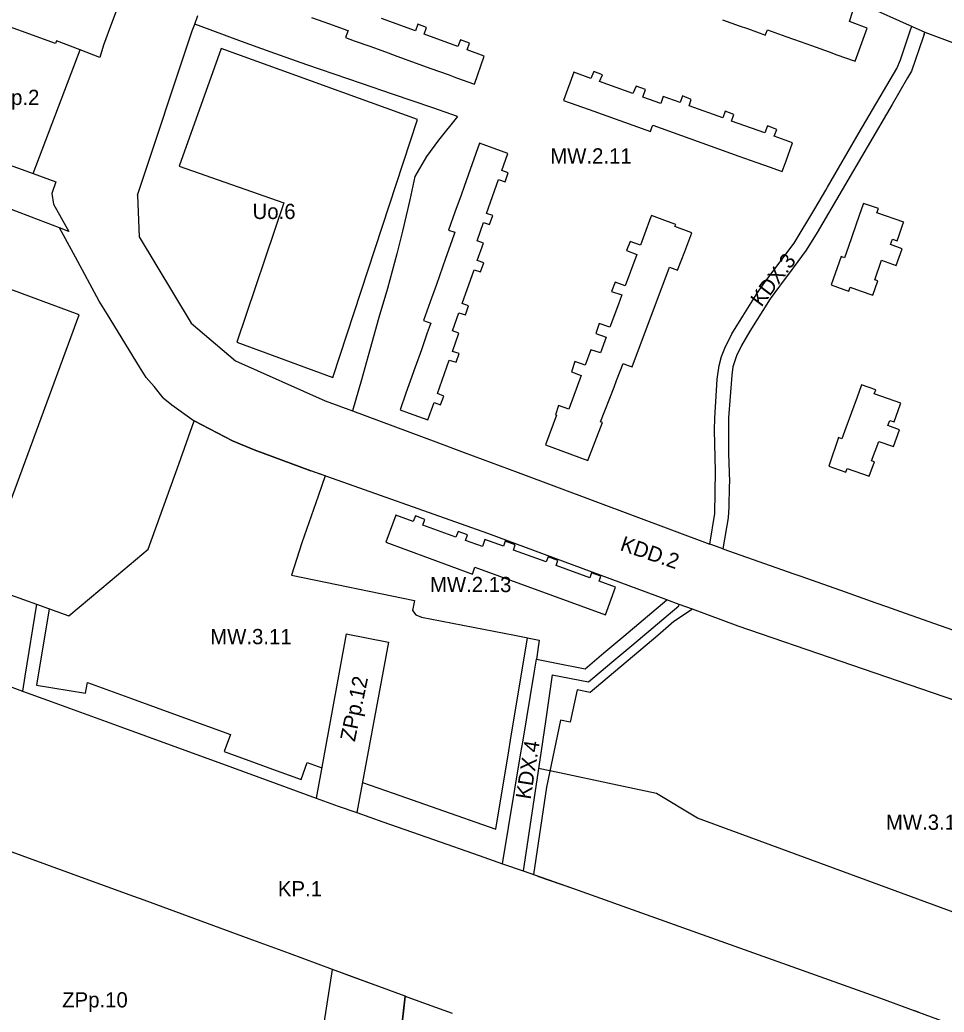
# Model space of a CAD drawing. Extents: x 7428239 to 7429836, y 5549133 to 5550853.
# Drawn here: x 7429012.7 to 7429316.4, y 5549745.6 to 5550071.7 of the extents above; entities that cross this region are included whole.
import ezdxf

# ---------------------------------------------------------------- set-up
doc = ezdxf.new("R2010")
doc.units = 0
for name, color, linetype in [('LIN_linia regulacyjna', 7, 'Continuous'), ('LIN_linie rozgraniczające', 7, 'Continuous'), ('LIN_nieprzekraczalna linia zabudowy', 7, 'Continuous'), ('LIN_obowiązująca linia zabudowy', 7, 'Continuous'), ('TXT_Oznaczenia Przeznaczenia', 7, 'Continuous')]:
    doc.layers.add(name, color=color, linetype=linetype)

msp = doc.modelspace()

# ---------------------------------------------------------------- linework, layer by layer
at = {"layer": 'LIN_linia regulacyjna'}
msp.add_lwpolyline([(7429383.84, 5549754.68), (7429367.89, 5549760.56), (7429360.9, 5549763.13), (7429350.66, 5549766.9), (7429332.99, 5549773.42), (7429318.45, 5549778.77), (7429315.16, 5549779.99), (7429235.41, 5549809.37), (7429221.85, 5549817.44), (7429207.39, 5549820.5), (7429189.98, 5549824.19), (7429183.11, 5549825.65)], dxfattribs=at)
at = {"layer": 'LIN_linie rozgraniczające'}
for p, q in [((7429048.11, 5550084.81), (7429042.17, 5550068.75)), ((7429070.18, 5550070.29), (7429071.18, 5550073.05)), ((7429042.17, 5550068.75), (7429040.94, 5550065.41)), ((7429051.4, 5550014.04), (7429069.36, 5550068.06)), ((7429069.36, 5550068.06), (7429070.18, 5550070.29)), ((7429075.21, 5550068.44), (7429070.18, 5550070.29)), ((7429085.48, 5550064.6), (7429075.21, 5550068.44)), ((7429040.94, 5550065.41), (7429040.18, 5550063.37)), ((7429094.96, 5550061.21), (7429085.48, 5550064.6)), ((7429309.49, 5550065.94), (7429305.69, 5550054.82)), ((7429309.83, 5550066.93), (7429309.49, 5550065.94)), ((7429039.01, 5550059.28), (7429032.54, 5550061.79)), ((7429040.18, 5550063.37), (7429039.01, 5550059.28)), ((7429107, 5550056.94), (7429094.96, 5550061.21)), ((7429300.88, 5550055.73), (7429302.04, 5550058.54)), ((7429124.92, 5550050.79), (7429107, 5550056.94)), ((7429288.53, 5550034.67), (7429300.88, 5550055.73)), ((7429305.69, 5550054.82), (7429304.33, 5550052.57)), ((7429304.33, 5550052.57), (7429299.34, 5550043.86)), ((7429135.1, 5550047.26), (7429124.92, 5550050.79)), ((7429148.42, 5550042.73), (7429135.1, 5550047.26)), ((7429156.54, 5550039.96), (7429148.42, 5550042.73)), ((7429299.34, 5550043.86), (7429274.66, 5550001.79)), ((7429156.54, 5550039.96), (7429150.28, 5550032.18)), ((7429278.13, 5550016.7), (7429288.53, 5550034.67)), ((7429150.28, 5550032.18), (7429146.35, 5550026.77)), ((7429146.35, 5550026.77), (7429142.5, 5550020.18)), ((7429017.02, 5550021.18), (7429024.56, 5550018.47)), ((7429024.56, 5550018.47), (7429023.19, 5550014.63)), ((7429142.5, 5550020.18), (7429140.81, 5550012.55)), ((7429273.95, 5550009.54), (7429277.48, 5550015.75)), ((7429277.48, 5550015.75), (7429278.13, 5550016.7)), ((7429023.19, 5550014.63), (7429023.8, 5550011.07)), ((7429051.4, 5550014.04), (7429051.87, 5550000.33)), ((7429140.81, 5550012.55), (7429138.4, 5550002.19)), ((7429023.8, 5550011.07), (7429028.8, 5550002.15)), ((7429267.13, 5549998.27), (7429273.95, 5550009.54)), ((7429028.8, 5550002.15), (7429025.73, 5550003.32)), ((7429138.4, 5550002.19), (7429136.57, 5549994.79)), ((7429051.87, 5550000.33), (7429068.96, 5549971.95)), ((7429274.66, 5550001.79), (7429271.05, 5549996.04)), ((7429257.18, 5549985.08), (7429267.13, 5549998.27)), ((7429271.05, 5549996.04), (7429266.84, 5549990.22)), ((7429136.57, 5549994.79), (7429133.46, 5549983.4)), ((7429266.84, 5549990.22), (7429262.28, 5549984.21)), ((7429133.46, 5549983.4), (7429130.67, 5549973.83)), ((7429254.62, 5549981.31), (7429257.18, 5549985.08)), ((7429262.28, 5549984.21), (7429259.23, 5549979.97)), ((7429250.21, 5549974.3), (7429254.62, 5549981.31)), ((7429259.23, 5549979.97), (7429252.6, 5549969.35)), ((7429130.67, 5549973.83), (7429127.19, 5549961.24)), ((7429246.65, 5549968.52), (7429250.21, 5549974.3)), ((7429068.96, 5549971.95), (7429083.61, 5549959.58)), ((7429252.6, 5549969.35), (7429249.84, 5549964.65)), ((7429244.32, 5549963.81), (7429246.65, 5549968.52)), ((7429243.21, 5549961.01), (7429244.32, 5549963.81)), ((7429249.84, 5549964.65), (7429248.21, 5549961.23)), ((7429083.61, 5549959.58), (7429113.02, 5549946.53)), ((7429127.19, 5549961.24), (7429124.91, 5549953.41)), ((7429242.45, 5549958.06), (7429243.21, 5549961.01)), ((7429248.21, 5549961.23), (7429246.97, 5549957.62)), ((7429241.85, 5549953.58), (7429242.45, 5549958.06)), ((7429246.97, 5549957.62), (7429246.63, 5549954.94)), ((7429124.91, 5549953.41), (7429122.03, 5549943.17)), ((7429241.04, 5549940.77), (7429241.85, 5549953.58)), ((7429246.63, 5549954.94), (7429245.58, 5549940.93)), ((7429059.76, 5549947.51), (7429056.86, 5549951.14)), ((7429113.02, 5549946.53), (7429122.03, 5549943.17)), ((7429122.03, 5549943.17), (7429149.33, 5549932.99)), ((7429240.93, 5549936.89), (7429241.04, 5549940.77)), ((7429245.58, 5549940.93), (7429245.6, 5549929.22)), ((7429064.9, 5549925.71), (7429070.03, 5549939.93)), ((7429241.24, 5549923.35), (7429240.93, 5549936.89)), ((7429149.33, 5549932.99), (7429158.67, 5549929.51)), ((7429158.67, 5549929.51), (7429176.43, 5549922.89)), ((7429245.6, 5549929.22), (7429245.85, 5549919.81)), ((7429054.82, 5549897.74), (7429064.9, 5549925.71)), ((7429113.02, 5549921.82), (7429110.7, 5549915.13)), ((7429176.43, 5549922.89), (7429239.44, 5549899.39)), ((7429241.07, 5549909.41), (7429241.24, 5549923.35)), ((7429245.76, 5549918.47), (7429245.61, 5549911.62)), ((7429245.85, 5549919.81), (7429245.76, 5549918.47)), ((7429110.7, 5549915.13), (7429105.4, 5549899.79)), ((7429245.61, 5549911.62), (7429245.41, 5549908.03)), ((7429239.44, 5549899.39), (7429241.07, 5549909.41)), ((7429245.41, 5549908.03), (7429243.7, 5549897.84)), ((7429042.36, 5549887.26), (7429054.82, 5549897.74)), ((7429241.61, 5549898.58), (7429239.44, 5549899.39)), ((7429243.7, 5549897.84), (7429241.61, 5549898.58)), ((7429243.7, 5549897.84), (7429266.98, 5549889.64)), ((7429266.98, 5549889.64), (7429269.34, 5549888.81)), ((7429269.34, 5549888.81), (7429283.86, 5549883.69)), ((7429002.91, 5549885.17), (7429018.14, 5549879.67)), ((7429028.75, 5549875.82), (7429042.36, 5549887.26)), ((7429283.86, 5549883.69), (7429293.99, 5549880.12)), ((7429018.14, 5549879.67), (7429014.36, 5549856.01)), ((7429018.14, 5549879.67), (7429028.75, 5549875.82)), ((7429211.17, 5549869.14), (7429225.33, 5549881.09)), ((7429213.75, 5549866.08), (7429229.19, 5549879.11)), ((7429229.19, 5549879.11), (7429229.36, 5549879.6)), ((7429293.99, 5549880.12), (7429297.52, 5549878.87)), ((7429297.52, 5549878.87), (7429302.08, 5549877.27)), ((7429302.08, 5549877.27), (7429312.94, 5549873.44)), ((7429316.41, 5549849.25), (7429248.77, 5549872.41)), ((7429312.94, 5549873.44), (7429354.21, 5549858.95)), ((7429119.89, 5549869.93), (7429110.07, 5549815.93)), ((7429119.89, 5549869.93), (7429133.88, 5549867.16)), ((7429204.62, 5549863.62), (7429211.17, 5549869.14)), ((7429133.88, 5549867.16), (7429123.44, 5549811.15)), ((7429207.2, 5549860.56), (7429213.75, 5549866.08)), ((7429198.44, 5549858.41), (7429204.62, 5549863.62)), ((7429181.79, 5549857.64), (7429182.44, 5549861.59)), ((7429182.44, 5549861.59), (7429188.44, 5549860.39)), ((7429188.44, 5549860.39), (7429198.44, 5549858.41)), ((7429199.55, 5549854.11), (7429207.2, 5549860.56)), ((7428997.96, 5549856.76), (7429013.57, 5549851.08)), ((7429014.36, 5549856.01), (7429013.57, 5549851.08)), ((7429187.66, 5549856.47), (7429199.55, 5549854.11)), ((7429013.57, 5549851.08), (7429022.96, 5549847.66)), ((7429332.07, 5549843.85), (7429316.41, 5549849.25)), ((7429022.96, 5549847.66), (7429045.92, 5549839.3)), ((7429045.92, 5549839.3), (7429062.14, 5549833.39)), ((7429062.14, 5549833.39), (7429079.28, 5549827.15)), ((7429079.28, 5549827.15), (7429096.92, 5549820.72)), ((7429096.92, 5549820.72), (7429110.07, 5549815.93)), ((7429110.07, 5549815.93), (7429117.33, 5549813.3)), ((7429117.33, 5549813.3), (7429123.44, 5549811.15)), ((7429123.44, 5549811.15), (7429132.02, 5549808.15)), ((7429132.02, 5549808.15), (7429148.64, 5549802.33)), ((7429037.75, 5549788.14), (7429004.61, 5549800.21)), ((7429148.64, 5549802.33), (7429163.59, 5549797.08)), ((7429163.59, 5549797.08), (7429171.32, 5549794.37)), ((7429171.32, 5549794.37), (7429178.09, 5549791.99)), ((7429178.09, 5549791.99), (7429194.32, 5549786.31)), ((7429050.18, 5549783.61), (7429037.75, 5549788.14)), ((7429053.54, 5549782.38), (7429050.18, 5549783.61)), ((7429070.18, 5549776.25), (7429053.54, 5549782.38)), ((7429088.02, 5549769.69), (7429070.18, 5549776.25)), ((7429221.57, 5549776.61), (7429229.22, 5549773.89)), ((7429229.22, 5549773.89), (7429295.48, 5549750.16)), ((7429101.28, 5549764.81), (7429088.02, 5549769.69)), ((7429115.45, 5549759.59), (7429101.28, 5549764.81)), ((7429123.08, 5549756.78), (7429115.45, 5549759.59)), ((7429130.67, 5549753.98), (7429123.08, 5549756.78)), ((7429139.27, 5549750.82), (7429130.67, 5549753.98)), ((7429139.27, 5549750.82), (7429131.04, 5549678.2)), ((7429295.48, 5549750.16), (7429306.73, 5549746.05)), ((7429307.99, 5549745.59), (7429306.73, 5549746.05))]:
    msp.add_line(p, q, dxfattribs=at)
for points in [[(7429286.07, 5550078.43), (7429310.06, 5550067.61), (7429344.3, 5550054.83)], [(7429032.54, 5550061.79), (7429024.72, 5550064.82), (7429024.38, 5550063.89), (7429000.78, 5550072.42), (7428999.81, 5550074.51), (7428995.7, 5550075.64), (7428992.26, 5550076.61), (7428977.71, 5550035.34), (7428978.55, 5550035.04), (7429017.02, 5550021.18)], [(7429302.04, 5550058.54), (7429305.39, 5550068.36), (7429305.79, 5550069.53)], [(7429309.83, 5550066.93), (7429310.06, 5550067.61)], [(7429017.02, 5550021.18), (7429032.54, 5550061.79)], [(7429025.73, 5550003.32), (7429016.5, 5550006.84), (7428985.48, 5550018.65)], [(7429056.86, 5549951.14), (7429054.19, 5549954.17), (7429051.97, 5549957.62), (7429041.46, 5549974.82), (7429038.8, 5549979.23), (7429031.03, 5549993.68), (7429027.03, 5550000.92), (7429025.73, 5550003.32)], [(7429059.76, 5549947.51), (7429062.62, 5549945.15), (7429070.03, 5549939.93), (7429082.61, 5549933.34), (7429089.73, 5549930.32), (7429108.31, 5549923.49)], [(7429248.77, 5549872.41), (7429233.7, 5549877.99), (7429229.36, 5549879.6), (7429225.33, 5549881.09), (7429166.48, 5549902.88), (7429108.31, 5549923.49)], [(7429105.4, 5549899.79), (7429101.92, 5549889.21)], [(7429101.92, 5549889.21), (7429142.34, 5549880.86), (7429141.77, 5549877.61), (7429142.76, 5549876.11), (7429144.67, 5549875.41), (7429175.2, 5549869.43), (7429183.37, 5549867.81), (7429182.44, 5549861.59)], [(7429171.32, 5549794.37), (7429177.34, 5549830.76), (7429177.92, 5549834.28), (7429181.79, 5549857.64)], [(7429187.66, 5549856.47), (7429185.38, 5549841.12), (7429183.51, 5549828.49), (7429178.09, 5549791.99)], [(7429194.32, 5549786.31), (7429221.57, 5549776.61)], [(7429100.53, 5549677.21), (7429111.74, 5549735.61), (7429115.45, 5549759.59)], [(7429154.81, 5549745.13), (7429140.01, 5549750.55), (7429139.27, 5549750.82)]]:
    msp.add_lwpolyline(points, dxfattribs=at)
at = {"layer": 'LIN_nieprzekraczalna linia zabudowy'}
msp.add_line((7429083.95, 5549965.73), (7429115.51, 5549954.19), dxfattribs=at)
for points in [[(7429143.41, 5550038.92), (7429078.86, 5550062.23), (7429065.09, 5550023.61), (7429099.41, 5550011.58), (7429083.95, 5549965.73)], [(7429115.51, 5549954.19), (7429143.41, 5550038.92)], [(7429032.2, 5549974.74), (7428968.53, 5549998.27), (7428938.39, 5549916.68), (7429002.06, 5549893.16), (7429032.2, 5549974.74)], [(7429113.02, 5549921.82), (7429108.31, 5549923.49), (7429089.73, 5549930.32), (7429082.61, 5549933.34), (7429070.03, 5549939.93)], [(7429022.29, 5549878.16), (7429018.13, 5549853), (7429034.32, 5549850.46), (7429034.89, 5549853.96), (7429049.34, 5549848.7), (7429065.56, 5549842.79), (7429081.87, 5549836.85), (7429079.83, 5549831.21), (7429090.36, 5549827.38), (7429094.47, 5549825.9), (7429105.08, 5549822.03), (7429107.13, 5549827.64), (7429111.89, 5549825.91)], [(7429233.7, 5549877.99), (7429227.6, 5549873.93), (7429222.34, 5549869.33)], [(7429376.87, 5549828.41), (7429371.43, 5549830.28), (7429345.57, 5549839.2), (7429329.74, 5549844.65), (7429316.41, 5549849.25), (7429248.77, 5549872.41), (7429233.7, 5549877.99)], [(7429169.14, 5549805.73), (7429173.39, 5549831.41), (7429173.97, 5549834.93), (7429179.55, 5549868.57)], [(7429222.34, 5549869.33), (7429200.14, 5549850.62), (7429195.8, 5549851.51), (7429193.56, 5549840.86), (7429190.36, 5549841.52), (7429185.7, 5549819.51), (7429181.44, 5549790.82)], [(7429125.29, 5549821.1), (7429135.32, 5549817.59), (7429151.95, 5549811.77), (7429166.9, 5549806.52), (7429169.14, 5549805.73)], [(7429182.79, 5549790.32), (7429194.32, 5549786.31), (7429221.57, 5549776.61)], [(7429221.57, 5549776.61), (7429229.22, 5549773.89), (7429295.48, 5549750.16), (7429306.73, 5549746.05), (7429307.99, 5549745.59)], [(7429100.53, 5549677.21), (7429129.64, 5549666.8), (7429131.04, 5549678.2), (7429139.27, 5549750.82), (7429130.67, 5549753.98), (7429115.45, 5549759.59)], [(7429307.99, 5549745.59), (7429325.83, 5549739.04), (7429343.2, 5549732.68), (7429360.02, 5549726.52), (7429374.1, 5549721.36)]]:
    msp.add_lwpolyline(points, dxfattribs=at)
at = {"layer": 'LIN_obowiązująca linia zabudowy'}
for points in [[(7429243.61, 5550071.71), (7429249.1, 5550069.74), (7429251.76, 5550068.79), (7429257.69, 5550066.66), (7429257.84, 5550067.08), (7429258.32, 5550068.4), (7429264.36, 5550066.24), (7429267.22, 5550065.21), (7429272.79, 5550063.22), (7429278.59, 5550061.15), (7429281.2, 5550060.21), (7429286.86, 5550058.18), (7429287.22, 5550058.05), (7429291.13, 5550068.98), (7429285.26, 5550071.08), (7429286.38, 5550074.55)], [(7429108.53, 5550072.48), (7429114.41, 5550070.35), (7429120.14, 5550068.27), (7429120.56, 5550068.12), (7429119.75, 5550065.83), (7429122.53, 5550064.83), (7429127.98, 5550062.86), (7429133.68, 5550060.79), (7429136.55, 5550059.76), (7429147.69, 5550055.72), (7429153.39, 5550053.66), (7429156.19, 5550052.65), (7429162.08, 5550050.51), (7429165.3, 5550059.75), (7429159.69, 5550061.8), (7429160.48, 5550064.03), (7429157.52, 5550065.08), (7429156.66, 5550062.91), (7429145.59, 5550066.95), (7429146.35, 5550069.15), (7429143.42, 5550070.24), (7429142.65, 5550068.02), (7429131.51, 5550072.09)]]:
    msp.add_lwpolyline(points, dxfattribs=at)
for points in [[(7429194.69, 5550054.43), (7429191.37, 5550045.2), (7429199.74, 5550042.19), (7429219.92, 5550034.93), (7429220.41, 5550036.31), (7429220.7, 5550037.09), (7429248.96, 5550026.92), (7429254.52, 5550024.92), (7429257.41, 5550023.88), (7429263.22, 5550021.79), (7429264.49, 5550025.33), (7429266.61, 5550031.21), (7429260.54, 5550033.4), (7429261.41, 5550035.68), (7429258.41, 5550036.82), (7429257.48, 5550034.5), (7429246.56, 5550038.43), (7429247.31, 5550040.57), (7429244.46, 5550041.61), (7429243.69, 5550039.46), (7429232.58, 5550043.46), (7429233.32, 5550045.54), (7429230.47, 5550046.68), (7429229.68, 5550044.5), (7429224.13, 5550046.5), (7429223.28, 5550044.14), (7429217.44, 5550046.24), (7429218.25, 5550048.77), (7429215.22, 5550049.91), (7429214.16, 5550047.42), (7429203.21, 5550051.36), (7429204.13, 5550053.59), (7429201.28, 5550054.73), (7429200.33, 5550052.4)], [(7429146.8, 5549940.22), (7429148.84, 5549945.94), (7429150.94, 5549945.15), (7429152.03, 5549948.02), (7429149.88, 5549948.85), (7429153.81, 5549959.88), (7429156.09, 5549959.16), (7429157.05, 5549961.98), (7429154.83, 5549962.74), (7429156.98, 5549968.76), (7429154.81, 5549969.53), (7429156.91, 5549975.43), (7429159.08, 5549974.79), (7429160.12, 5549977.67), (7429158, 5549978.48), (7429161.95, 5549989.57), (7429164.1, 5549988.87), (7429165.17, 5549991.77), (7429163.02, 5549992.57), (7429165.06, 5549998.29), (7429162.92, 5549999.05), (7429165.04, 5550005.09), (7429167.06, 5550004.39), (7429168.13, 5550007.34), (7429166.08, 5550008.06), (7429169.98, 5550019.18), (7429172.12, 5550018.42), (7429173.15, 5550021.42), (7429171.03, 5550022.16), (7429172.99, 5550027.76), (7429163.7, 5550031.16), (7429160.63, 5550022.49), (7429158.64, 5550016.88), (7429157.66, 5550014.1), (7429155.66, 5550008.45), (7429153.59, 5550002.61), (7429155.65, 5550001.88), (7429155.55, 5550001.6), (7429154.66, 5549999.08), (7429152.59, 5549993.26), (7429150.57, 5549987.56), (7429149.56, 5549984.69), (7429147.53, 5549978.97), (7429145.36, 5549972.84), (7429147.72, 5549972), (7429147.54, 5549971.48), (7429146.59, 5549968.79), (7429144.63, 5549963.26), (7429142.62, 5549957.58), (7429140.54, 5549951.72), (7429139.57, 5549948.97), (7429137.62, 5549943.48), (7429140.66, 5549942.4)], [(7429289.9, 5550011.37), (7429289.79, 5550011.05), (7429288.51, 5550007.37), (7429284.94, 5549997.15), (7429283.65, 5549993.45), (7429282.54, 5549993.86), (7429279.34, 5549984.59), (7429283.41, 5549983.11), (7429285.1, 5549982.49), (7429285.56, 5549983.81), (7429288.83, 5549982.66), (7429292.99, 5549981.19), (7429294.64, 5549985.88), (7429293.6, 5549986.22), (7429295.82, 5549992.65), (7429300.64, 5549990.95), (7429302.59, 5549996.42), (7429298.82, 5549997.82), (7429299.43, 5549999.58), (7429301.01, 5549999.04), (7429301.65, 5550000.89), (7429303, 5550004.81), (7429303.14, 5550005.22), (7429294.33, 5550008.3), (7429294.84, 5550009.68)], [(7429228.21, 5550004.4), (7429225.52, 5550005.4), (7429220.21, 5550007.36), (7429220.06, 5550006.94), (7429217.93, 5550001.21), (7429216.61, 5549997.66), (7429213.2, 5549998.86), (7429212.04, 5549995.84), (7429215.46, 5549994.55), (7429211.64, 5549984.28), (7429208.26, 5549985.48), (7429207.09, 5549982.44), (7429210.53, 5549981.28), (7429209.41, 5549978.29), (7429206.59, 5549970.69), (7429203.1, 5549971.84), (7429202.01, 5549968.62), (7429205.37, 5549967.42), (7429203.44, 5549962.2), (7429200.33, 5549963.27), (7429198.45, 5549958.21), (7429195.03, 5549959.35), (7429193.92, 5549956.05), (7429197.19, 5549954.84), (7429193.06, 5549943.76), (7429189.74, 5549944.93), (7429188.66, 5549941.93), (7429189.08, 5549941.78), (7429185.47, 5549932.01), (7429199.38, 5549926.89), (7429204.2, 5549939.36), (7429203.54, 5549939.61), (7429207.93, 5549950.98), (7429208.77, 5549953.15), (7429210.94, 5549958.75), (7429212.24, 5549958.25), (7429213.91, 5549957.61), (7429226.19, 5549990.36), (7429228.81, 5549989.38), (7429231.18, 5549995.53), (7429233.55, 5550001.68), (7429227.92, 5550003.81)], [(7429294.9, 5549933.16), (7429299.72, 5549931.46), (7429301.7, 5549936.9), (7429297.9, 5549938.33), (7429298.53, 5549940.05), (7429299.94, 5549939.54), (7429300.63, 5549941.46), (7429301.95, 5549945.17), (7429302.14, 5549945.7), (7429293.46, 5549948.81), (7429293.95, 5549950.08), (7429289.28, 5549951.73), (7429289.16, 5549951.41), (7429287.8, 5549947.67), (7429284.15, 5549937.62), (7429282.84, 5549934), (7429281.7, 5549934.4), (7429278.49, 5549925.02), (7429284.14, 5549923.02), (7429284.58, 5549924.25), (7429291.79, 5549921.7), (7429293.54, 5549926.4), (7429292.58, 5549926.76)], [(7429133, 5549900), (7429161.45, 5549889.52), (7429162.22, 5549891.79), (7429205.11, 5549876.12), (7429208.45, 5549885.2), (7429203.06, 5549887.17), (7429203.57, 5549888.82), (7429200.55, 5549889.92), (7429200.02, 5549888.28), (7429188.9, 5549892.34), (7429189.48, 5549894.06), (7429186.33, 5549895.21), (7429185.67, 5549893.53), (7429174.92, 5549897.45), (7429175.5, 5549899.17), (7429172.2, 5549900.33), (7429171.58, 5549898.68), (7429165.54, 5549900.88), (7429164.67, 5549898.59), (7429159.11, 5549900.6), (7429159.78, 5549902.45), (7429156.69, 5549903.55), (7429155.98, 5549901.73), (7429145.12, 5549905.65), (7429145.75, 5549907.5), (7429142.68, 5549908.65), (7429141.96, 5549906.79), (7429136.21, 5549908.86)]]:
    msp.add_lwpolyline(points, close=True, dxfattribs=at)

# ---------------------------------------------------------------- texts
at = {"layer": 'TXT_Oznaczenia Przeznaczenia'}
for s, p in [('ZPp.2', (7429001.28, 5550043.69)), ('MW.2.11', (7429186.99, 5550024.46)), ('Uo.6', (7429089.17, 5550006.22)), ('MW.2.13', (7429147.46, 5549883.62)), ('MW.3.11', (7429075.25, 5549866.51)), ('MW.3.12', (7429297.27, 5549805.51)), ('KP.1', (7429097.48, 5549783.64)), ('ZPp.10', (7429026.6, 5549747.14))]:
    msp.add_text(s, height=5, dxfattribs=at).set_placement(p)
for s, rotation, p in [('KDX.3', 53.024, (7429256.37, 5549977.06)), ('KDD.2', 341.2281, (7429209.62, 5549897.45)), ('ZPp.12', 78.2644, (7429122.76, 5549834.28)), ('KDX.4', 80.9362, (7429180.5, 5549815.31))]:
    msp.add_text(s, height=5, rotation=rotation, dxfattribs=at).set_placement(p)

doc.saveas('drawing.dxf')
